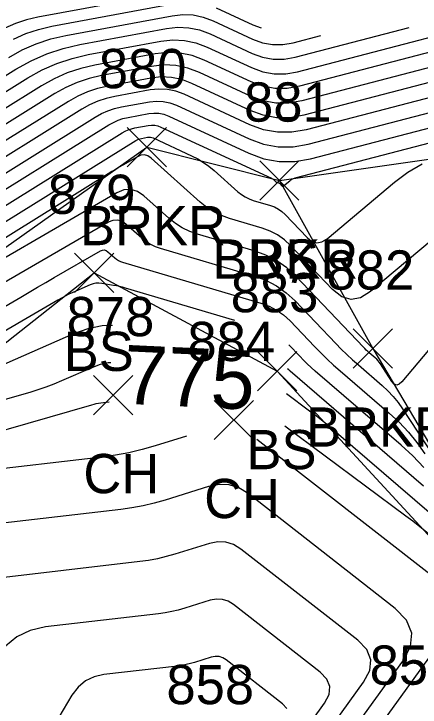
# Model space of a CAD drawing. Extents: x 1650836 to 1652450, y 332578 to 333908.
# Drawn here: x 1652180.5 to 1652201.18, y 332848.28 to 332883.6 of the extents above; entities that cross this region are included whole.
import ezdxf

# ---------------------------------------------------------------- set-up
doc = ezdxf.new("R2010")
doc.units = 0
for name, color, linetype in [('L_A', 7, 'Continuous'), ('L_I', 7, 'Continuous'), ('L_TIC', 7, 'Continuous'), ('LAWE', 7, 'Continuous'), ('LELB', 7, 'Continuous'), ('LSOGCMA', 7, 'Continuous'), ('LSOGCMA_T', 7, 'Continuous'), ('LSOGCMI', 7, 'Continuous')]:
    doc.layers.add(name, color=color, linetype=linetype)

msp = doc.modelspace()

# ---------------------------------------------------------------- linework, layer by layer
at = {"layer": 'L_TIC'}
for points in [[(1652186.273, 332875.813), (1652188.273, 332877.813)], [(1652188.273, 332875.813), (1652186.273, 332877.813)], [(1652193.015, 332874.109), (1652195.015, 332876.109)], [(1652195.015, 332874.109), (1652193.015, 332876.109)], [(1652193.015, 332874.109), (1652195.015, 332876.109)], [(1652195.015, 332874.109), (1652193.015, 332876.109)], [(1652183.593, 332869.407), (1652185.593, 332871.407)], [(1652185.593, 332869.407), (1652183.593, 332871.407)], [(1652197.78, 332865.55), (1652199.78, 332867.55)], [(1652199.78, 332865.55), (1652197.78, 332867.55)], [(1652192.9, 332864.398), (1652194.9, 332866.398)], [(1652194.9, 332864.398), (1652192.9, 332866.398)], [(1652184.548, 332863.178), (1652186.548, 332865.178)], [(1652186.548, 332863.178), (1652184.548, 332865.178)], [(1652190.698, 332861.91), (1652192.698, 332863.91)], [(1652192.698, 332861.91), (1652190.698, 332863.91)]]:
    msp.add_lwpolyline(points, dxfattribs=at)
at = {"layer": 'LAWE'}
msp.add_lwpolyline([(1652166.593, 332836.388), (1652160.434, 332848.646), (1652165.686, 332861.189), (1652174.634, 332867.863), (1652187.273, 332876.813), (1652194.015, 332875.109), (1652198.78, 332866.55), (1652205.312, 332855.518), (1652223.542, 332850.363), (1652239.899, 332850.316), (1652254.339, 332849.604), (1652281.376, 332840.252)], dxfattribs=at)
at = {"layer": 'LELB'}
for points in [[(1652194.015, 332875.109), (1652221.23, 332879.003), (1652254.339, 332849.604)], [(1652273.911, 332830.103), (1652248.33, 332832.215), (1652238.99, 332835.863), (1652205.84, 332837.591), (1652191.874, 332835.507), (1652180.705, 332833.239), (1652166.498, 332840.6), (1652166.784, 332849.708), (1652168.84, 332859.33), (1652177.78, 332865.033), (1652184.593, 332870.407), (1652193.9, 332865.398), (1652204.385, 332854.011), (1652221.637, 332847.232), (1652240.383, 332847.355), (1652253.69, 332847.74), (1652279.741, 332838.109)]]:
    msp.add_lwpolyline(points, dxfattribs=at)
at = {"layer": 'LSOGCMA'}
for points in [[(1652177.789, 332874.076), (1652184.645, 332878.341), (1652184.959, 332878.517), (1652185.285, 332878.662), (1652185.623, 332878.775), (1652185.974, 332878.856), (1652187.4, 332879.121), (1652187.753, 332879.159), (1652188.099, 332879.143), (1652188.439, 332879.073), (1652188.771, 332878.947), (1652192.481, 332877.225), (1652193.215, 332876.955), (1652193.961, 332876.819), (1652194.719, 332876.819), (1652195.49, 332876.954), (1652213.806, 332881.729)], [(1652185.439, 332865.82), (1652185.294, 332865.813), (1652184.89, 332865.732), (1652184.494, 332865.59), (1652182.923, 332864.899), (1652182.528, 332864.733), (1652182.128, 332864.58), (1652181.723, 332864.442), (1652181.313, 332864.317), (1652177.663, 332863.269)], [(1652202.499, 332857.459), (1652196.908, 332862.278), (1652196.578, 332862.558), (1652196.242, 332862.832), (1652195.902, 332863.099), (1652195.557, 332863.361), (1652194.375, 332864.241)]]:
    msp.add_lwpolyline(points, dxfattribs=at)
at = {"layer": 'LSOGCMI'}
for points in [[(1652189.143, 332884.807), (1652181.716, 332883.432), (1652181.136, 332883.296), (1652180.576, 332883.109), (1652180.036, 332882.87), (1652179.516, 332882.579), (1652177.477, 332881.311), (1652176.983, 332880.976), (1652176.517, 332880.608), (1652176.081, 332880.204), (1652175.675, 332879.767), (1652173.561, 332877.312), (1652173.046, 332876.815), (1652172.468, 332876.444), (1652171.825, 332876.199), (1652171.119, 332876.082), (1652166.499, 332875.74), (1652165.485, 332875.652), (1652164.474, 332875.54), (1652163.465, 332875.402), (1652162.46, 332875.24), (1652157.382, 332874.355), (1652156.333, 332874.026), (1652155.549, 332873.451)], [(1652180.481, 332882.316), (1652181.107, 332882.594), (1652181.757, 332882.811), (1652182.43, 332882.968), (1652188.853, 332884.158)], [(1652177.616, 332878.095), (1652181.217, 332880.335), (1652181.94, 332880.741), (1652182.692, 332881.074), (1652183.471, 332881.334), (1652184.279, 332881.523), (1652187.984, 332882.209), (1652188.59, 332882.275), (1652189.185, 332882.248), (1652189.769, 332882.126), (1652190.34, 332881.911), (1652192.601, 332880.861), (1652193.171, 332880.651), (1652193.75, 332880.546), (1652194.339, 332880.546), (1652194.937, 332880.651), (1652207.689, 332883.975)], [(1652190.802, 332883.911), (1652192.673, 332883.043), (1652193.082, 332882.892)], [(1652208.912, 332883.526), (1652195.048, 332879.911), (1652194.415, 332879.801), (1652193.792, 332879.801), (1652193.18, 332879.912), (1652192.577, 332880.134), (1652190.186, 332881.244), (1652189.581, 332881.472), (1652188.965, 332881.6), (1652188.336, 332881.629), (1652187.694, 332881.559), (1652184.618, 332880.989), (1652183.902, 332880.822), (1652183.21, 332880.591), (1652182.544, 332880.296), (1652181.902, 332879.937), (1652177.65, 332877.291)], [(1652180.239, 332881.378), (1652180.926, 332881.763), (1652181.639, 332882.078), (1652182.378, 332882.326), (1652183.145, 332882.504), (1652188.563, 332883.508), (1652189.1, 332883.567), (1652189.627, 332883.543), (1652190.143, 332883.435), (1652190.648, 332883.244), (1652192.649, 332882.316), (1652193.153, 332882.13), (1652193.666, 332882.037), (1652194.187, 332882.037), (1652194.716, 332882.129), (1652196.134, 332882.499)], [(1652210.136, 332883.077), (1652195.158, 332879.172), (1652194.491, 332879.055), (1652193.835, 332879.055), (1652193.188, 332879.173), (1652192.553, 332879.407), (1652189.943, 332880.618), (1652189.351, 332880.842), (1652188.746, 332880.968), (1652188.129, 332880.996), (1652187.499, 332880.927), (1652184.957, 332880.456), (1652184.332, 332880.31), (1652183.729, 332880.109), (1652183.148, 332879.851), (1652182.588, 332879.538), (1652177.685, 332876.488)], [(1652177.581, 332878.899), (1652180.601, 332880.778), (1652181.371, 332881.209), (1652182.17, 332881.563), (1652183, 332881.84), (1652183.859, 332882.041), (1652188.273, 332882.858), (1652188.845, 332882.921), (1652189.406, 332882.895), (1652189.956, 332882.781), (1652190.494, 332882.578), (1652192.625, 332881.588), (1652193.162, 332881.39), (1652193.708, 332881.291), (1652194.263, 332881.291), (1652194.827, 332881.39), (1652200.632, 332882.903)], [(1652211.359, 332882.628), (1652195.269, 332878.433), (1652194.567, 332878.31), (1652193.877, 332878.31), (1652193.197, 332878.433), (1652192.529, 332878.679), (1652189.553, 332880.061), (1652189.047, 332880.252), (1652188.531, 332880.359), (1652188.004, 332880.384), (1652187.466, 332880.325), (1652185.296, 332879.923), (1652184.763, 332879.799), (1652184.248, 332879.626), (1652183.751, 332879.407), (1652183.274, 332879.139), (1652177.719, 332875.684)], [(1652212.582, 332882.179), (1652195.379, 332877.693), (1652194.643, 332877.565), (1652193.919, 332877.565), (1652193.206, 332877.694), (1652192.505, 332877.952), (1652189.162, 332879.504), (1652188.743, 332879.662), (1652188.315, 332879.751), (1652187.878, 332879.772), (1652187.433, 332879.723), (1652185.635, 332879.39), (1652185.193, 332879.287), (1652184.766, 332879.144), (1652184.355, 332878.962), (1652183.959, 332878.74), (1652177.754, 332874.88)], [(1652177.799, 332873.257), (1652185.331, 332877.943), (1652185.563, 332878.073), (1652185.804, 332878.179), (1652186.054, 332878.263), (1652186.313, 332878.323), (1652187.367, 332878.519), (1652187.628, 332878.547), (1652187.884, 332878.535), (1652188.134, 332878.483), (1652188.38, 332878.39), (1652192.457, 332876.498), (1652193.224, 332876.215), (1652194.003, 332876.074), (1652194.796, 332876.074), (1652195.601, 332876.215), (1652215.029, 332881.28)], [(1652177.036, 332871.958), (1652186.016, 332877.544), (1652186.166, 332877.628), (1652186.322, 332877.697), (1652186.484, 332877.751), (1652186.652, 332877.79), (1652187.334, 332877.916), (1652187.503, 332877.935), (1652187.668, 332877.927), (1652187.83, 332877.893), (1652187.989, 332877.834), (1652193.612, 332875.223), (1652193.64, 332875.209), (1652193.666, 332875.193), (1652193.692, 332875.175), (1652193.715, 332875.155), (1652193.825, 332875.057), (1652193.841, 332875.044), (1652193.858, 332875.034), (1652193.876, 332875.025), (1652193.895, 332875.018), (1652193.974, 332874.995), (1652193.993, 332874.988), (1652194.011, 332874.978), (1652194.027, 332874.967), (1652194.042, 332874.953), (1652194.143, 332874.847), (1652194.165, 332874.83), (1652194.187, 332874.823), (1652194.21, 332874.827), (1652194.234, 332874.842), (1652194.543, 332875.102), (1652194.605, 332875.148), (1652194.67, 332875.187), (1652194.74, 332875.218), (1652194.813, 332875.241), (1652216.252, 332880.831)], [(1652176.274, 332870.658), (1652186.702, 332877.145), (1652186.77, 332877.183), (1652186.841, 332877.215), (1652186.915, 332877.239), (1652186.991, 332877.257), (1652187.301, 332877.314), (1652187.377, 332877.323), (1652187.452, 332877.319), (1652187.526, 332877.304), (1652187.598, 332877.277), (1652189.55, 332876.371), (1652189.857, 332876.214), (1652190.151, 332876.036), (1652190.43, 332875.836), (1652190.696, 332875.616), (1652191.906, 332874.531), (1652192.082, 332874.39), (1652192.27, 332874.27), (1652192.471, 332874.173), (1652192.684, 332874.097), (1652193.56, 332873.838), (1652193.772, 332873.761), (1652193.968, 332873.658), (1652194.148, 332873.531), (1652194.313, 332873.378), (1652195.435, 332872.201), (1652195.677, 332872.01), (1652195.927, 332871.936), (1652196.183, 332871.982), (1652196.445, 332872.146), (1652199.872, 332875.027), (1652200.554, 332875.539), (1652201.279, 332875.968)], [(1652205.456, 332875.166), (1652198.656, 332869.449), (1652198.155, 332869.136), (1652197.666, 332869.049), (1652197.19, 332869.189), (1652196.727, 332869.556), (1652194.585, 332871.803), (1652194.27, 332872.095), (1652193.925, 332872.338), (1652193.55, 332872.534), (1652193.147, 332872.682), (1652191.473, 332873.176), (1652191.067, 332873.321), (1652190.683, 332873.507), (1652190.323, 332873.735), (1652189.987, 332874.006), (1652187.48, 332876.252), (1652187.316, 332876.364), (1652187.146, 332876.414), (1652186.969, 332876.4), (1652186.786, 332876.324), (1652186.04, 332875.892), (1652185.854, 332875.783), (1652185.669, 332875.673), (1652185.484, 332875.561), (1652185.301, 332875.448), (1652175.511, 332869.358)], [(1652203.148, 332868.299), (1652200.254, 332864.846), (1652200.12, 332864.726), (1652199.992, 332864.691), (1652199.868, 332864.741), (1652199.749, 332864.876), (1652199.164, 332865.77), (1652199.106, 332865.852), (1652199.043, 332865.93), (1652198.974, 332866.003), (1652198.9, 332866.072), (1652198.592, 332866.337), (1652198.516, 332866.404), (1652198.442, 332866.473), (1652198.37, 332866.544), (1652198.299, 332866.616), (1652194.857, 332870.228), (1652194.391, 332870.658), (1652193.882, 332871.018), (1652193.329, 332871.307), (1652192.733, 332871.525), (1652189.849, 332872.378), (1652189.45, 332872.519), (1652189.073, 332872.703), (1652188.72, 332872.927), (1652188.389, 332873.192), (1652187.113, 332874.335), (1652186.788, 332874.558), (1652186.45, 332874.657), (1652186.098, 332874.63), (1652185.734, 332874.477), (1652176.431, 332869.089)], [(1652178.518, 332869.061), (1652185.32, 332873), (1652185.552, 332873.097), (1652185.776, 332873.114), (1652185.991, 332873.052), (1652186.199, 332872.91), (1652187.012, 332872.181), (1652187.222, 332872.012), (1652187.447, 332871.87), (1652187.687, 332871.753), (1652187.941, 332871.663), (1652192.743, 332870.243), (1652193.327, 332870.03), (1652193.868, 332869.747), (1652194.367, 332869.394), (1652194.824, 332868.972), (1652196.884, 332866.811), (1652197.163, 332866.525), (1652197.448, 332866.247), (1652197.741, 332865.975), (1652198.04, 332865.711), (1652199.25, 332864.668), (1652199.542, 332864.398), (1652199.813, 332864.11), (1652200.063, 332863.803), (1652200.292, 332863.478), (1652202.596, 332859.959)], [(1652177.574, 332867.26), (1652180.856, 332869.174), (1652181.28, 332869.422), (1652181.705, 332869.669), (1652182.131, 332869.916), (1652182.556, 332870.162), (1652184.906, 332871.523), (1652185.005, 332871.565), (1652185.102, 332871.572), (1652185.195, 332871.546), (1652185.284, 332871.484), (1652185.634, 332871.171), (1652185.724, 332871.098), (1652185.821, 332871.037), (1652185.924, 332870.986), (1652186.034, 332870.947), (1652193.072, 332868.868), (1652193.49, 332868.715), (1652193.877, 332868.512), (1652194.234, 332868.26), (1652194.561, 332867.958), (1652195.808, 332866.649), (1652196.123, 332866.326), (1652196.447, 332866.011), (1652196.777, 332865.704), (1652197.116, 332865.406), (1652199.6, 332863.264), (1652200.11, 332862.793), (1652200.583, 332862.29), (1652201.02, 332861.754), (1652201.42, 332861.187)], [(1652191.751, 332867.979), (1652186.175, 332869.627), (1652186.027, 332869.668), (1652185.878, 332869.705), (1652185.728, 332869.738), (1652185.577, 332869.766), (1652184.971, 332869.869), (1652184.82, 332869.884), (1652184.673, 332869.876), (1652184.528, 332869.847), (1652184.386, 332869.796), (1652183.494, 332869.404), (1652183.3, 332869.315), (1652183.108, 332869.221), (1652182.919, 332869.121), (1652182.733, 332869.016), (1652178.557, 332866.58)], [(1652185.528, 332867.73), (1652185.001, 332867.705), (1652184.263, 332867.557), (1652183.539, 332867.297), (1652178.43, 332865.049)], [(1652201.372, 332860.486), (1652200.816, 332861.076), (1652200.218, 332861.63), (1652195.841, 332865.402), (1652195.636, 332865.583), (1652195.437, 332865.768), (1652195.242, 332865.958), (1652195.051, 332866.153), (1652194.491, 332866.741)], [(1652201.358, 332859.544), (1652194.566, 332865.399), (1652194.496, 332865.461), (1652194.434, 332865.518)], [(1652175.84, 332861.209), (1652184.466, 332863.686), (1652184.58, 332863.716), (1652184.695, 332863.742), (1652184.811, 332863.763), (1652184.929, 332863.779), (1652185.346, 332863.827)], [(1652194.299, 332862.616), (1652200.46, 332858.031), (1652200.813, 332857.763), (1652201.162, 332857.488), (1652201.506, 332857.208), (1652201.845, 332856.921), (1652203.64, 332855.373), (1652203.747, 332855.274), (1652203.847, 332855.168), (1652203.938, 332855.056), (1652204.022, 332854.937), (1652204.343, 332854.447), (1652204.43, 332854.334), (1652204.531, 332854.237), (1652204.647, 332854.158), (1652204.776, 332854.096), (1652218.277, 332848.851), (1652218.642, 332848.717), (1652219.011, 332848.598), (1652219.385, 332848.493), (1652219.763, 332848.402), (1652221.283, 332848.067)], [(1652189.286, 332862.088), (1652187.695, 332861.59), (1652187.025, 332861.398), (1652186.349, 332861.238), (1652185.665, 332861.109), (1652184.975, 332861.012), (1652178.521, 332860.261)], [(1652198.481, 332844.753), (1652198.384, 332845.524), (1652198.372, 332845.837), (1652198.418, 332846.135), (1652198.521, 332846.419), (1652198.681, 332846.688), (1652202.288, 332851.69), (1652202.757, 332852.583), (1652202.837, 332853.42), (1652202.527, 332854.202), (1652201.827, 332854.929), (1652192.872, 332861.92)], [(1652197.556, 332846.819), (1652200.298, 332850.621), (1652200.687, 332851.362), (1652200.753, 332852.056), (1652200.496, 332852.705), (1652199.915, 332853.307), (1652192.425, 332859.156), (1652191.956, 332859.446), (1652191.464, 332859.604), (1652190.947, 332859.63), (1652190.406, 332859.523), (1652188.196, 332858.832), (1652187.64, 332858.673), (1652187.079, 332858.54), (1652186.512, 332858.433), (1652185.94, 332858.353), (1652174.354, 332857.004)], [(1652196.431, 332846.951), (1652198.308, 332849.553), (1652198.617, 332850.141), (1652198.669, 332850.693), (1652198.465, 332851.208), (1652198.004, 332851.686), (1652192.055, 332856.331), (1652191.683, 332856.562), (1652191.291, 332856.687), (1652190.881, 332856.707), (1652190.452, 332856.623), (1652188.696, 332856.074), (1652188.255, 332855.947), (1652187.809, 332855.841), (1652187.359, 332855.757), (1652186.904, 332855.693), (1652179.122, 332854.787), (1652178.075, 332854.553), (1652177.163, 332854.11), (1652176.386, 332853.458), (1652175.745, 332852.597), (1652173.451, 332848.734), (1652173.056, 332847.799)], [(1652195.021, 332846.687), (1652196.318, 332848.484), (1652196.547, 332848.92), (1652196.585, 332849.329), (1652196.434, 332849.71), (1652196.092, 332850.065), (1652191.685, 332853.506), (1652191.409, 332853.677), (1652191.119, 332853.77), (1652190.815, 332853.785), (1652190.497, 332853.722), (1652189.196, 332853.316), (1652188.869, 332853.222), (1652188.539, 332853.143), (1652188.206, 332853.081), (1652187.869, 332853.034), (1652182.103, 332852.362), (1652181.327, 332852.189), (1652180.651, 332851.86), (1652180.076, 332851.377), (1652179.601, 332850.739), (1652177.902, 332847.878)], [(1652194.403, 332848.213), (1652194.181, 332848.444), (1652191.315, 332850.681), (1652191.136, 332850.792), (1652190.947, 332850.853), (1652190.749, 332850.863), (1652190.543, 332850.822), (1652189.697, 332850.557), (1652189.484, 332850.496), (1652189.269, 332850.445), (1652189.053, 332850.405), (1652188.834, 332850.374), (1652185.084, 332849.938), (1652184.58, 332849.825), (1652184.14, 332849.611), (1652183.766, 332849.297), (1652183.457, 332848.882), (1652182.352, 332847.021)]]:
    msp.add_lwpolyline(points, dxfattribs=at)

# ---------------------------------------------------------------- texts
at = {"layer": 'L_A'}
for s, p in [('BRKR', (1652183.864, 332871.813)), ('BRKR', (1652190.605, 332870.109)), ('BS', (1652192.456, 332870.109)), ('BS', (1652183.034, 332865.407)), ('BRKR', (1652195.371, 332861.55)), ('BS', (1652192.341, 332860.398)), ('CH', (1652184.037, 332859.178)), ('CH', (1652190.186, 332857.91))]:
    msp.add_text(s, height=2, dxfattribs=at).set_placement(p)
at = {"layer": 'L_I'}
for s, p in [('880', (1652184.824, 332879.813)), ('881', (1652192.22, 332878.109)), ('881', (1652192.22, 332878.109)), ('879', (1652182.223, 332873.407)), ('882', (1652196.418, 332869.55)), ('883', (1652191.538, 332868.398)), ('878', (1652183.186, 332867.178)), ('884', (1652189.336, 332865.91)), ('853', (1652198.615, 332849.421)), ('858', (1652188.265, 332848.429))]:
    msp.add_text(s, height=2, dxfattribs=at).set_placement(p)
at = {"layer": 'LSOGCMA_T'}
for rotation, p in [(357.3282, (1652186.016, 332863.742)), (238.1521, (1652203.507, 332850.001))]:
    msp.add_text('775', height=3, rotation=rotation, dxfattribs=at).set_placement(p)

doc.saveas('drawing.dxf')
